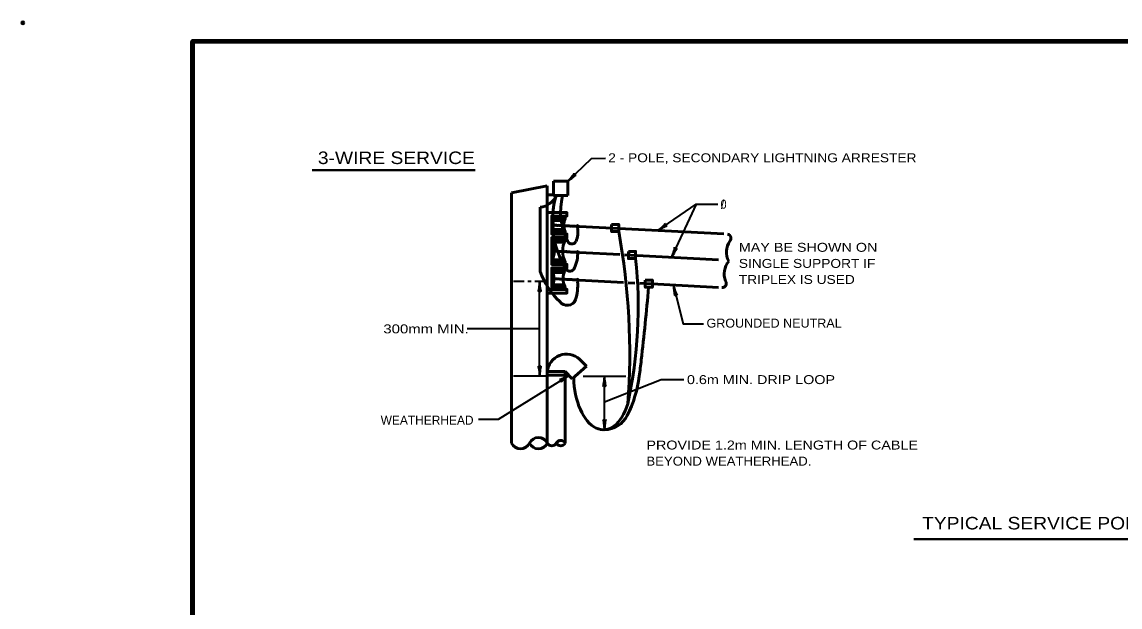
# Model space of a CAD drawing. Extents: x -33 to 680, y -7 to 447.
# Drawn here: x -32.7 to 274.7, y 283.1 to 446.7 of the extents above; entities that cross this region are included whole.
import ezdxf

# ---------------------------------------------------------------- set-up
doc = ezdxf.new("R2010")
doc.units = 0
doc.header["$PDMODE"] = 32
doc.header["$PDSIZE"] = 0.5
doc.layers.add('1', color=7, linetype='Continuous', lineweight=53)

msp = doc.modelspace()

# ---------------------------------------------------------------- hatches: boundary and pattern name
at = {"layer": '1'}
for points in [[(123.331, 389.564, 1), (122.331, 389.564, 1)], [(123.331, 382.319, 1), (122.331, 382.319, 1)], [(123.301, 374.562, 1), (122.301, 374.562, 1)]]:
    msp.add_hatch(color=256, dxfattribs=at).paths.add_polyline_path(points)

# ---------------------------------------------------------------- linework, layer by layer
at = {"layer": '1', "lineweight": 40}
for p, q in [((48.553, 405.318), (94.098, 405.318)), ((216.934, 302.073), (306.519, 302.073))]:
    msp.add_line(p, q, dxfattribs=at)
at = {"layer": '1'}
for p, q in [((114.342, 400.924), (104.342, 398.924)), ((114.342, 400.924), (114.342, 328.924)), ((116.092, 402.174), (116.092, 398.174)), ((116.092, 402.174), (120.092, 402.174)), ((120.092, 402.174), (120.092, 398.174)), ((104.342, 398.924), (104.342, 328.924)), ((114.342, 398.424), (116.092, 398.424)), ((116.092, 398.174), (120.092, 398.174)), ((112.342, 394.924), (112.342, 376.924)), ((119.342, 391.674), (115.592, 391.674)), ((119.121, 391.174), (115.813, 391.174)), ((119.342, 391.674), (119.342, 392.424)), ((115.592, 388.174), (119.342, 388.174)), ((115.813, 388.674), (119.121, 388.674)), ((119.342, 388.174), (119.342, 387.424)), ((123.331, 389.569), (163.773, 387.45)), ((119.342, 385.674), (115.592, 385.674)), ((119.12, 385.174), (115.814, 385.174)), ((119.342, 385.674), (119.342, 386.424)), ((123.33, 382.285), (134.673, 381.69)), ((135.922, 381.625), (162.275, 380.244)), ((115.592, 379.674), (119.342, 379.674)), ((115.814, 380.174), (119.12, 380.174)), ((119.342, 379.674), (119.342, 378.924)), ((119.342, 377.174), (115.592, 377.174)), ((119.104, 376.674), (115.829, 376.674)), ((119.342, 377.174), (119.342, 377.924)), ((115.592, 372.674), (119.342, 372.674)), ((115.829, 373.174), (119.104, 373.174)), ((119.342, 372.674), (119.342, 371.924)), ((123.299, 374.518), (135.645, 373.871)), ((136.994, 373.801), (138.847, 373.703)), ((140.154, 373.635), (162.249, 372.477)), ((123.342, 352.424), (125.342, 350.424)), ((119.342, 348.924), (114.342, 348.924)), ((119.342, 347.924), (114.342, 347.924)), ((119.342, 348.924), (119.342, 328.924)), ((119.342, 348.924), (121.342, 346.924)), ((125.342, 350.424), (121.342, 346.924))]:
    msp.add_line(p, q, dxfattribs=at)
at = {"layer": '1', "lineweight": 35}
for p, q in [((156.003, 395.805), (162.04, 395.805)), ((107.842, 374.174), (104.842, 374.174)), ((109.842, 374.174), (108.842, 374.174)), ((113.842, 374.174), (110.842, 374.174)), ((112.195, 347.674), (112.195, 374.174)), ((112.195, 360.924), (91.946, 360.924)), ((113.842, 347.674), (104.842, 347.674)), ((124.342, 347.674), (136.342, 347.674)), ((130.342, 332.674), (130.342, 347.674))]:
    msp.add_line(p, q, dxfattribs=at)
at = {"layer": '1', "lineweight": 158}
msp.add_lwpolyline([(674.767, 441.411), (15.017, 441.328), (15.1, 2.994)], dxfattribs=at)
at = {"layer": '1', "lineweight": 35}
for points in [[(120.092, 402.174), (126.701, 408.599), (130.591, 408.617)], [(145.292, 388.418), (156.003, 395.805), (149.141, 380.932)], [(149.64, 373.037), (152.332, 362.347), (158.043, 362.347)], [(120.438, 347.883), (100.605, 335.534), (95.106, 335.534)], [(130.326, 340.45), (146.239, 346.771), (152.558, 346.771)]]:
    msp.add_lwpolyline(points, dxfattribs=at)
at = {"layer": '1'}
for points in [[(114.342, 393.424), (119.842, 393.424), (119.842, 392.424), (115.592, 392.424), (115.592, 387.424), (119.842, 387.424), (119.842, 386.424), (115.592, 386.424), (115.592, 378.924), (119.842, 378.924), (119.842, 377.924), (115.592, 377.924), (115.592, 371.924), (119.842, 371.924), (119.842, 370.924), (114.342, 370.924)], [(115.779, 389.924), (115.868, 389.917), (115.936, 389.917), (116.005, 389.909), (116.05, 389.909), (116.103, 389.909), (116.156, 389.909), (116.217, 389.917), (116.338, 389.94), (116.361, 389.932), (116.399, 389.917), (116.437, 389.924), (116.46, 389.917), (116.581, 389.917), (116.649, 389.856), (116.642, 389.849), (116.672, 389.871), (116.733, 389.849), (116.793, 389.849), (116.854, 389.879), (116.862, 389.887), (116.922, 389.902), (116.953, 389.887), (116.991, 389.864), (117.021, 389.856), (117.173, 389.841), (117.226, 389.856), (117.332, 389.834), (117.362, 389.864), (117.423, 389.864), (117.537, 389.826), (117.552, 389.826), (117.605, 389.826), (117.832, 389.849), (117.84, 389.849), (117.893, 389.834), (118.022, 389.811), (118.144, 389.818), (118.234, 389.818), (118.318, 389.826), (118.394, 389.834), (118.454, 389.803), (118.568, 389.796), (118.591, 389.75), (118.674, 389.742), (118.819, 389.735), (118.856, 389.75), (118.947, 389.78), (119.069, 389.803), (119.145, 389.765), (119.152, 389.765), (119.175, 389.72), (119.395, 389.773), (119.418, 389.75), (119.448, 389.742), (119.577, 389.742), (119.6, 389.735), (119.706, 389.758), (119.751, 389.75), (119.82, 389.735), (119.858, 389.75), (119.941, 389.742), (120.04, 389.75), (120.153, 389.742), (120.214, 389.712), (120.252, 389.674), (120.26, 389.667), (120.388, 389.682), (120.442, 389.674), (120.563, 389.674), (120.616, 389.659), (120.715, 389.667), (120.98, 389.667), (121.018, 389.667), (121.086, 389.674), (121.177, 389.667), (121.215, 389.644), (121.291, 389.636), (121.412, 389.606), (121.526, 389.629), (121.572, 389.636), (121.685, 389.629), (121.769, 389.613), (121.799, 389.575), (121.898, 389.583), (122.042, 389.583), (122.148, 389.575), (122.194, 389.598), (122.3, 389.591), (122.376, 389.613)], [(115.383, 382.673), (115.472, 382.666), (115.541, 382.666), (115.609, 382.659), (115.654, 382.659), (115.708, 382.659), (115.761, 382.659), (115.821, 382.666), (115.943, 382.689), (115.965, 382.681), (116.003, 382.666), (116.041, 382.674), (116.064, 382.666), (116.185, 382.666), (116.254, 382.606), (116.246, 382.598), (116.276, 382.621), (116.337, 382.598), (116.398, 382.598), (116.459, 382.628), (116.466, 382.636), (116.527, 382.651), (116.557, 382.636), (116.595, 382.613), (116.625, 382.606), (116.777, 382.59), (116.83, 382.606), (116.936, 382.583), (116.967, 382.613), (117.027, 382.613), (117.141, 382.575), (117.156, 382.575), (117.209, 382.575), (117.437, 382.598), (117.444, 382.598), (117.498, 382.583), (117.626, 382.56), (117.748, 382.568), (117.839, 382.568), (117.922, 382.575), (117.998, 382.583), (118.059, 382.553), (118.173, 382.545), (118.195, 382.499), (118.279, 382.492), (118.423, 382.484), (118.461, 382.499), (118.552, 382.53), (118.673, 382.553), (118.749, 382.515), (118.757, 382.515), (118.779, 382.469), (118.999, 382.522), (119.022, 382.499), (119.052, 382.492), (119.181, 382.492), (119.204, 382.484), (119.31, 382.507), (119.356, 382.499), (119.424, 382.484), (119.462, 382.499), (119.545, 382.492), (119.644, 382.499), (119.758, 382.492), (119.819, 382.462), (119.856, 382.424), (119.864, 382.416), (119.993, 382.431), (120.046, 382.424), (120.167, 382.424), (120.221, 382.408), (120.319, 382.416), (120.584, 382.416), (120.623, 382.416), (120.691, 382.424), (120.782, 382.416), (120.82, 382.393), (120.895, 382.386), (121.017, 382.355), (121.131, 382.378), (121.176, 382.386), (121.29, 382.378), (121.373, 382.363), (121.404, 382.325), (121.502, 382.332), (121.646, 382.332), (121.753, 382.325), (121.798, 382.348), (121.904, 382.34), (121.98, 382.363)], [(121.98, 382.363), (122.174, 382.352), (122.244, 382.335), (122.296, 382.326), (122.402, 382.344)], [(115.92, 374.924), (116.009, 374.917), (116.077, 374.917), (116.145, 374.909), (116.191, 374.909), (116.244, 374.909), (116.297, 374.909), (116.358, 374.917), (116.479, 374.94), (116.502, 374.932), (116.54, 374.917), (116.578, 374.924), (116.6, 374.917), (116.722, 374.917), (116.79, 374.856), (116.783, 374.849), (116.813, 374.871), (116.874, 374.849), (116.934, 374.849), (116.995, 374.879), (117.002, 374.887), (117.063, 374.902), (117.093, 374.887), (117.131, 374.864), (117.162, 374.856), (117.313, 374.841), (117.367, 374.856), (117.473, 374.834), (117.503, 374.864), (117.564, 374.864), (117.677, 374.826), (117.693, 374.826), (117.746, 374.826), (117.973, 374.849), (117.981, 374.849), (118.034, 374.834), (118.163, 374.811), (118.284, 374.818), (118.375, 374.818), (118.459, 374.826), (118.535, 374.834), (118.595, 374.803), (118.709, 374.796), (118.732, 374.75), (118.815, 374.742), (118.959, 374.735), (118.997, 374.75), (119.088, 374.78), (119.21, 374.803), (119.285, 374.765), (119.293, 374.765), (119.316, 374.72), (119.536, 374.773), (119.558, 374.75), (119.589, 374.742), (119.718, 374.742), (119.741, 374.735), (119.847, 374.758), (119.892, 374.75), (119.96, 374.735), (119.998, 374.75), (120.082, 374.742), (120.18, 374.75), (120.294, 374.742), (120.355, 374.712), (120.393, 374.674), (120.4, 374.667), (120.529, 374.682), (120.582, 374.674), (120.704, 374.674), (120.757, 374.659), (120.855, 374.667), (121.121, 374.667), (121.159, 374.667), (121.227, 374.674), (121.318, 374.667), (121.356, 374.644), (121.432, 374.636), (121.553, 374.606), (121.667, 374.629), (121.713, 374.636), (121.826, 374.629), (121.91, 374.613), (121.94, 374.575), (122.039, 374.583), (122.183, 374.583), (122.289, 374.575), (122.334, 374.598), (122.441, 374.591), (122.516, 374.613)]]:
    msp.add_lwpolyline(points, dxfattribs=at)
for points in [[(132.319, 390.098), (134.319, 390.098), (134.319, 388.098), (132.319, 388.098)], [(137.061, 382.565), (139.061, 382.565), (139.061, 380.565), (137.061, 380.565)], [(141.774, 374.55), (143.774, 374.55), (143.774, 372.55), (141.774, 372.55)]]:
    msp.add_lwpolyline(points, close=True, dxfattribs=at)
at = {"layer": '1', "lineweight": 13}
for centre in [(122.831, 389.564), (122.831, 382.319), (122.801, 374.562)]:
    msp.add_circle(centre, 0.5, dxfattribs=at)
at = {"layer": '1'}
for centre, radius, start, end in [((111.831, 400.371), 5.471, 275.35282, 336.32248), ((140.863, 390.914), 25.095, 163.18371, 211.99973), ((137.125, 393.751), 19.054, 166.57684, 205.98789), ((112.309, 389.924), 3.72, 331.93494, 28.06506), ((122.624, 389.924), 3.72, 151.93494, 208.06506), ((115.504, 388.037), 7.39, 338.28432, 8.16262), ((-49.496, 354.235), 186.908, 355.61418, 10.4382), ((164.611, 386.278), 1.147, 314.46081, 81.61314), ((109.51, 382.674), 6.782, 333.74432, 26.25569), ((125.424, 382.674), 6.782, 153.74431, 206.25568), ((121.211, 386.025), 1.364, 207.17977, 328.05521), ((170.123, 382.388), 5.621, 146.88569, 207.1631), ((113.045, 382.149), 9.819, 331.25897, 358.40344), ((11.494, 367.092), 128.277, 347.78093, 6.02914), ((169.48, 376.272), 5.621, 140.8369, 201.11431), ((133.838, 384.911), 22.932, 200.38305, 225.6141), ((111.503, 374.924), 4.667, 331.17388, 28.82612), ((123.43, 374.924), 4.667, 151.17388, 208.82612), ((120.691, 378.326), 1.317, 212.63552, 316.97562), ((108.376, 373.165), 14.472, 343.68787, 3.62999), ((-744.562, 452.114), 890.834, 353.55933, 354.87476), ((163.28, 373.613), 1.147, 266.38686, 33.53919), ((119.875, 370.022), 2.562, 215.81165, 338.90815), ((119.703, 348.459), 5.382, 47.45902, 175.04199), ((44.516, 363.118), 96.753, 350.82752, 353.51226), ((108.279, 351.188), 31.945, 332.97577, 353.72112), ((130.216, 339.985), 7.312, 270.98195, 333.07352), ((111.842, 327.732), 2.77, 25.49727, 154.50273), ((115.592, 329.58), 1.412, 207.68943, 332.31057), ((118.092, 328.268), 1.412, 27.68943, 152.31057), ((118.092, 329.58), 1.412, 207.68943, 332.31057), ((106.842, 330.116), 2.77, 205.49727, 334.50273), ((111.842, 330.116), 2.77, 205.49727, 334.50273)]:
    msp.add_arc(centre, radius, start, end, dxfattribs=at)
at = {"layer": '1', "lineweight": 40}
for centre, major_axis, ratio, start_param, end_param in [((120.681, 403.133), (-1.172, -1.357), 0.122415, 0.8963533, 3.1415927), ((121.043, 402.803), (1.382, 1.098), 0.07063, 6.2823074, 8.5597026), ((146.034, 389.265), (-1.381, -1.142), 0.122415, 0.8963533, 3.1415927), ((146.034, 389.265), (-1.381, -1.142), 0.122415, 0.8963533, 3.1415927), ((146.335, 388.88), (1.546, 0.853), 0.07063, 6.2823074, 8.5597026), ((146.335, 388.88), (1.546, 0.853), 0.07063, 6.2823074, 8.5597026), ((149.347, 382.039), (-0.606, -1.687), 0.122415, 0.8963533, 3.1415927), ((149.803, 381.861), (-0.895, -1.521), 0.07063, 3.1407148, 5.41811), ((111.984, 373.053), (0.176, 1.756), 0.07063, 3.1407148, 5.41811), ((111.984, 373.053), (0.176, 1.756), 0.07063, 3.1407148, 5.41811), ((112.472, 373.083), (-0.156, 1.786), 0.122415, 0.8963533, 3.1415927), ((112.472, 373.083), (-0.156, 1.786), 0.122415, 0.8963533, 3.1415927), ((149.709, 371.899), (-0.259, 1.746), 0.07063, 3.1407148, 5.41811), ((149.709, 371.899), (-0.259, 1.746), 0.07063, 3.1407148, 5.41811), ((150.175, 372.046), (-0.587, 1.694), 0.122415, 0.8963533, 3.1415927), ((150.175, 372.046), (-0.587, 1.694), 0.122415, 0.8963533, 3.1415927), ((111.919, 348.765), (0.156, -1.786), 0.122415, 0.8963533, 3.1415927), ((112.407, 348.794), (-0.176, -1.756), 0.07063, 3.1407148, 5.41811), ((119.375, 347.47), (-1.584, -0.779), 0.07063, 6.2823074, 8.5597026), ((119.658, 347.072), (1.433, 1.076), 0.122415, 0.8963533, 3.1415927), ((130.13, 346.553), (0.176, 1.756), 0.07063, 3.1407148, 5.41811), ((130.13, 346.553), (0.176, 1.756), 0.07063, 3.1407148, 5.41811), ((130.618, 346.583), (-0.156, 1.786), 0.122415, 0.8963533, 3.1415927), ((130.618, 346.583), (-0.156, 1.786), 0.122415, 0.8963533, 3.1415927), ((130.065, 333.765), (0.156, -1.786), 0.122415, 0.8963533, 3.1415927), ((130.065, 333.765), (0.156, -1.786), 0.122415, 0.8963533, 3.1415927), ((130.553, 333.794), (-0.176, -1.756), 0.07063, 3.1407148, 5.41811), ((130.553, 333.794), (-0.176, -1.756), 0.07063, 3.1407148, 5.41811)]:
    msp.add_ellipse(centre, major_axis=major_axis, ratio=ratio, start_param=start_param, end_param=end_param, dxfattribs=at)
at = {"layer": '1'}
msp.add_ellipse((129.78, 347.464), major_axis=(-0.386, 14.798), ratio=0.544805, start_param=1.5707963, end_param=4.1650301, dxfattribs=at)
msp.add_point((-32.483, 446.494), dxfattribs=at)

# ---------------------------------------------------------------- texts
for s, height, width, p in [('3-WIRE SERVICE', 3.5, 1.15, (50.106, 407)), ('2 - POLE, SECONDARY LIGHTNING ARRESTER', 2.5, 1.15, (131.385, 407.51)), ('0', 2.5, 0.9, (162.852, 394.512)), ('MAY BE SHOWN ON', 2.5, 1.2, (167.948, 382.454)), ('SINGLE SUPPORT IF', 2.5, 1.15, (167.948, 377.954)), ('TRIPLEX IS USED', 2.5, 1.15, (167.948, 373.454)), ('GROUNDED NEUTRAL', 2.5, 1.05, (158.903, 361.25)), ('300mm MIN.', 2.5, 1.25, (68.432, 359.637)), ('0.6m MIN. DRIP LOOP', 2.5, 1.2, (153.425, 345.448)), ('PROVIDE 1.2m MIN. LENGTH OF CABLE', 2.5, 1.2, (142.087, 327.146)), ('BEYOND WEATHERHEAD.', 2.5, 1.1, (142.087, 322.646)), ('TYPICAL SERVICE POLE HEADS', 3.5, 1.15, (219.26, 304.788))]:
    msp.add_text(s, height=height, dxfattribs=dict(at, width=width)).set_placement(p)
for s, p in [('/', (162.946, 394.496)), ('WEATHERHEAD', (67.687, 334.106))]:
    msp.add_text(s, height=2.5, dxfattribs=at).set_placement(p)

doc.saveas('drawing.dxf')
